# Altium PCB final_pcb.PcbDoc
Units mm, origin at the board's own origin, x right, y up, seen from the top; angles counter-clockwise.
Board outline 84.84 x 58.93 mm, 2 copper layers (Top Layer, Bottom Layer); 68 components, 48 nets, 240 pads, 41 vias.
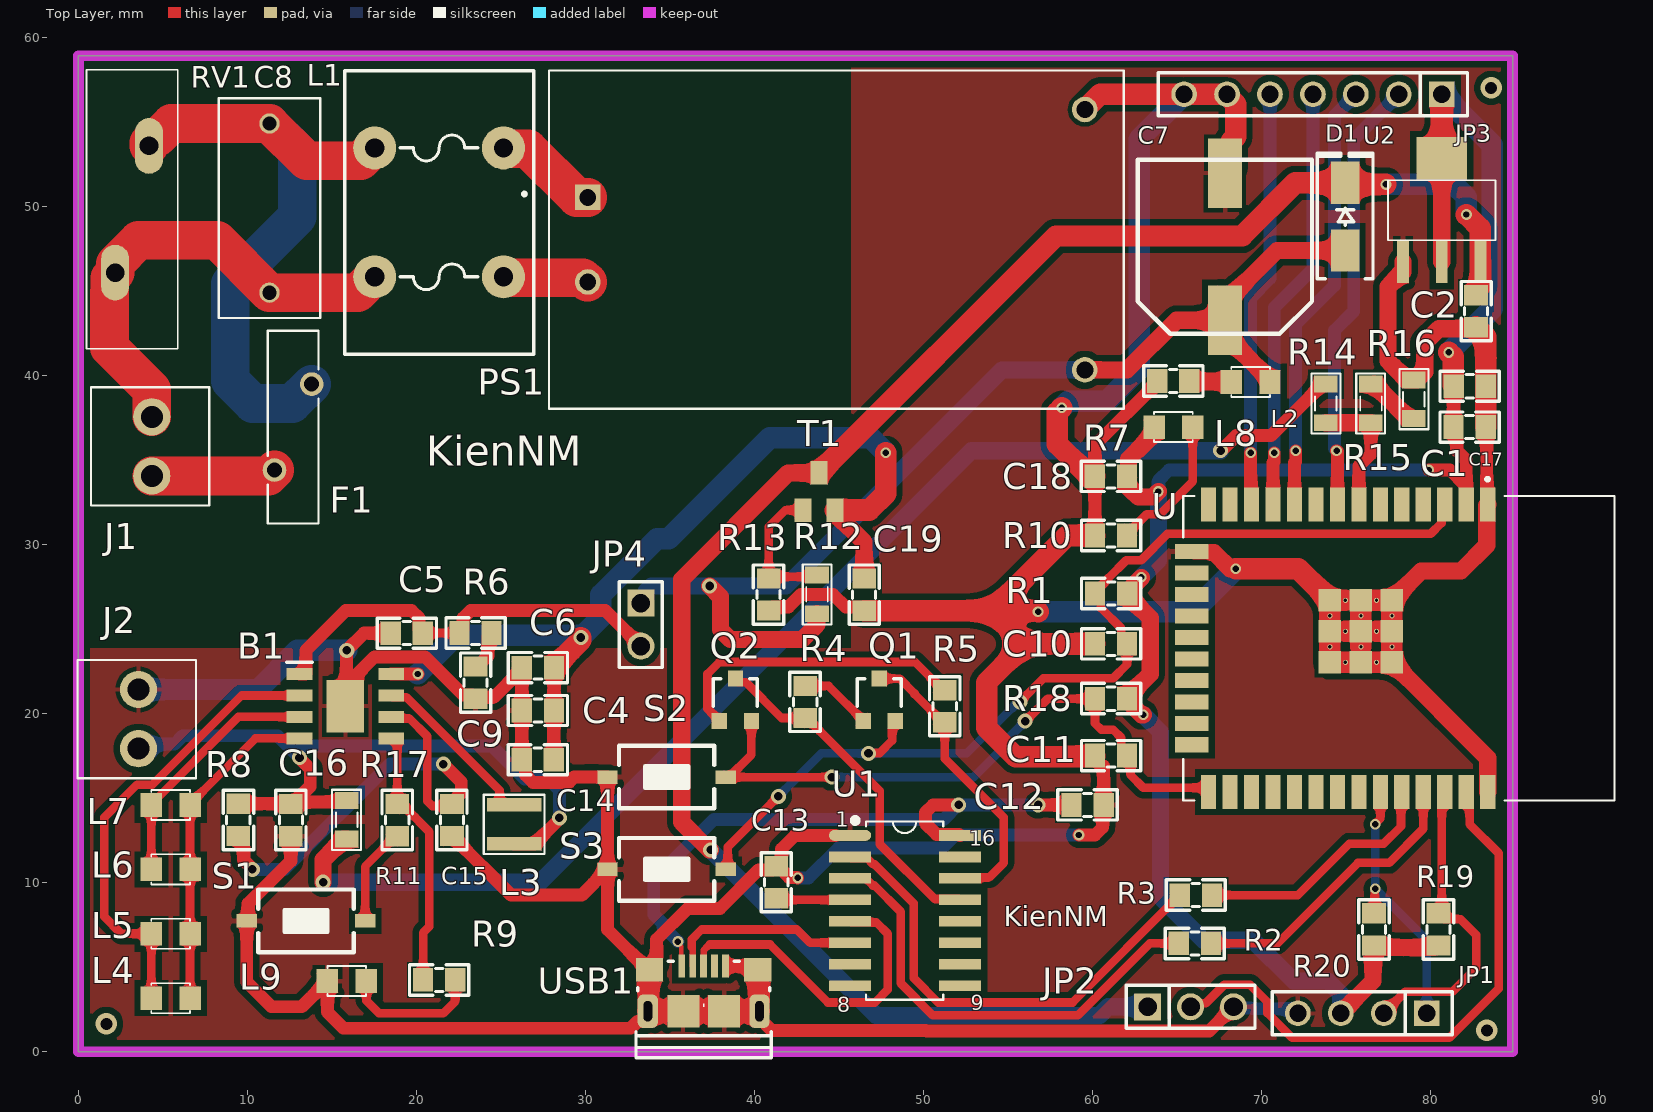
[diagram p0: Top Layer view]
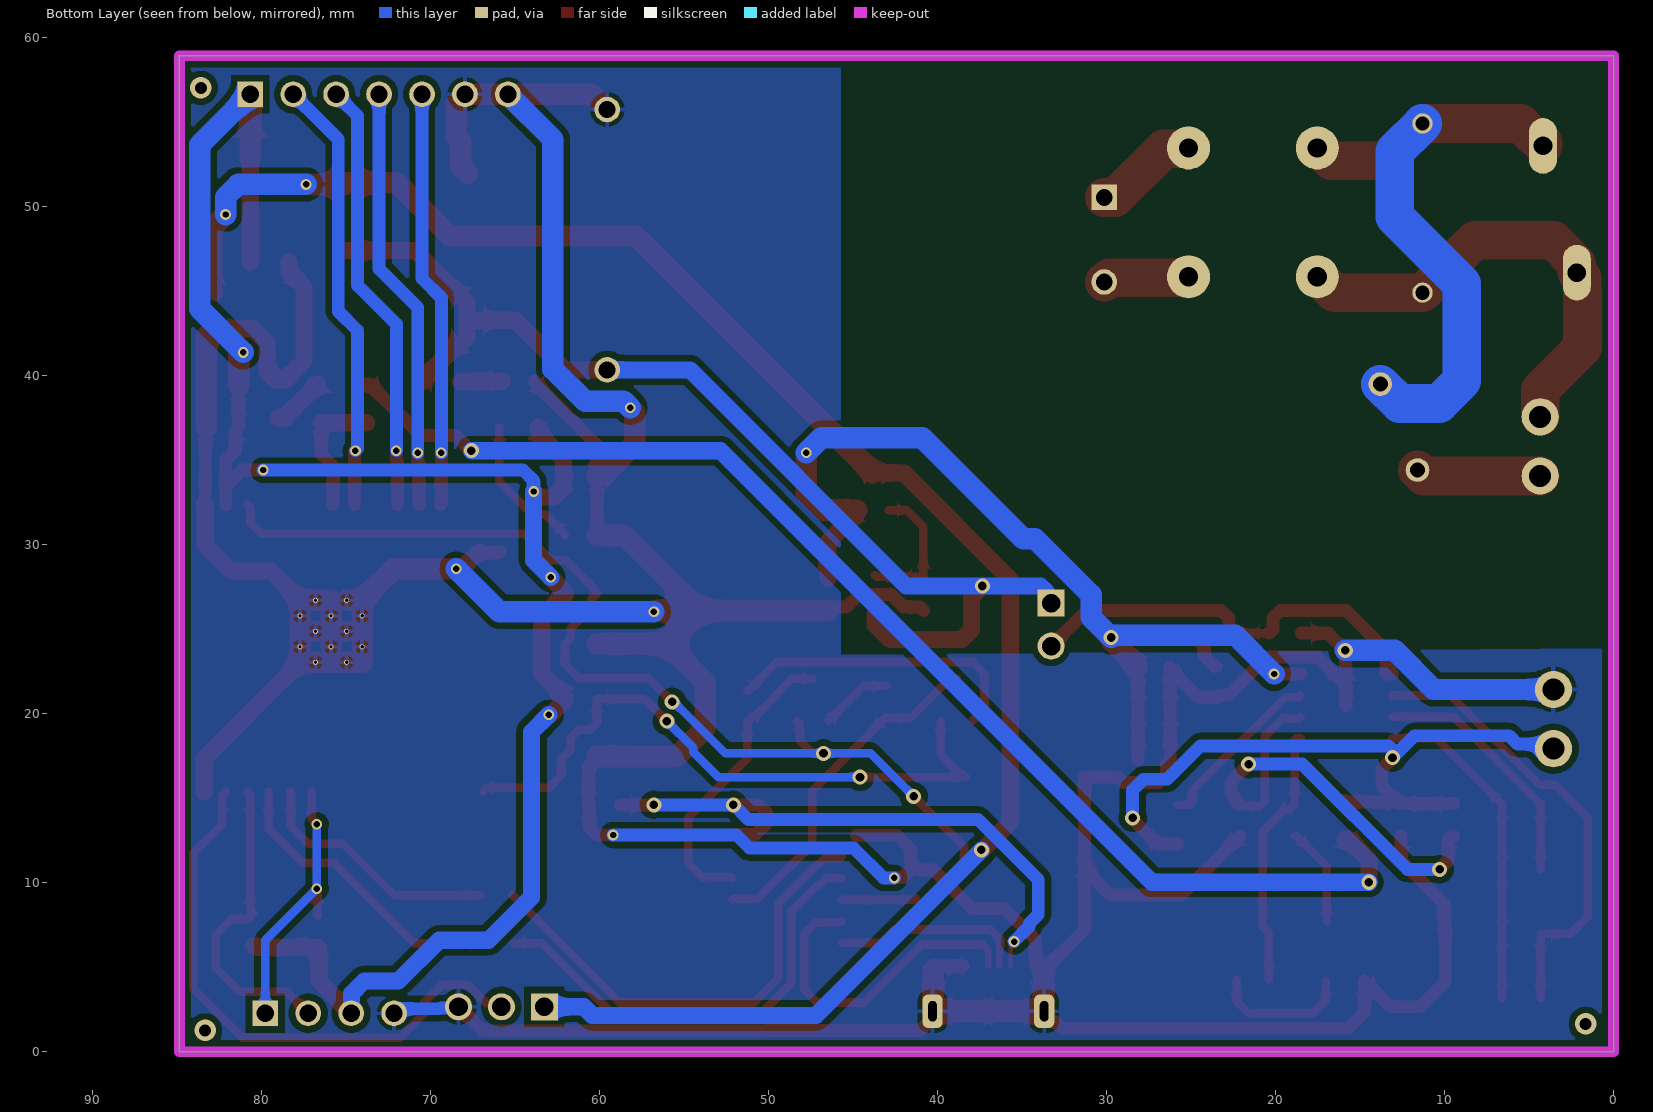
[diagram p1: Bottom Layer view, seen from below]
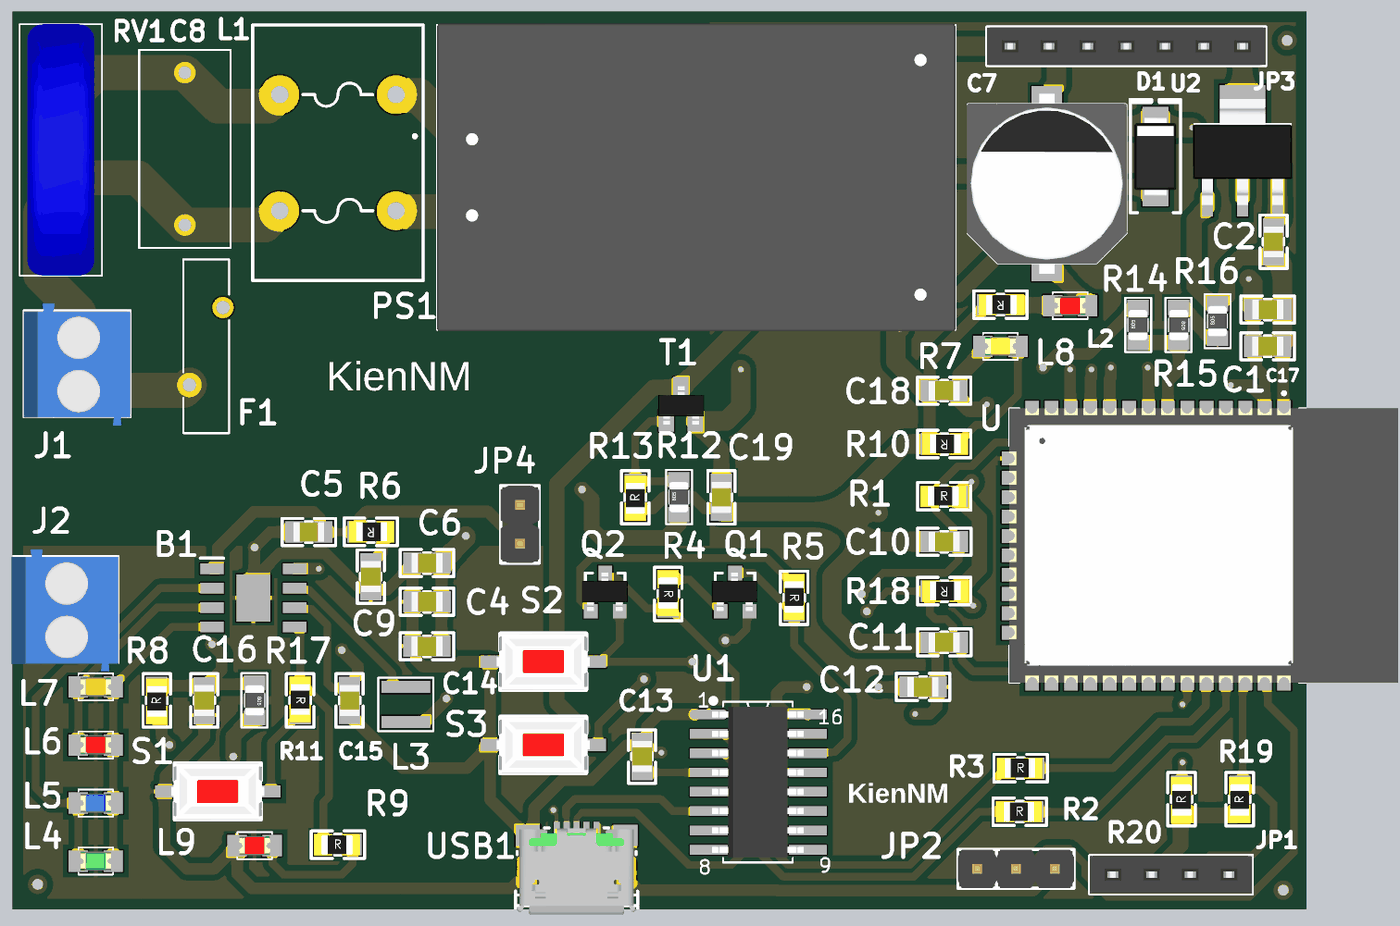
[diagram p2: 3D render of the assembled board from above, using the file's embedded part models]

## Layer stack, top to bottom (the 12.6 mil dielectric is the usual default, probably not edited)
Top Solder: solder mask 0.0102, Solder Resist, Dk 3.5
Top Layer: signal copper 0.0356
Dielectric 1: dielectric 0.32, FR-4, Dk 4.8
Bottom Layer: signal copper 0.0356
Bottom Solder: solder mask 0.0102, Solder Resist, Dk 3.5

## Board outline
0,0 84.836,0 84.836,58.928 0,58.928

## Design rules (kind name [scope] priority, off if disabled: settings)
Clearance [All] p1: gap=0.254 ignorepadtopadclearanceinfootprint=FALSE
PolygonConnect [All] p1: connectstyle=Relief reliefconductorwidth=0.254 reliefentries=4 polygonreliefangle="90 Angle" airgapwidth=0.254
RoutingVias [All] p1: holewidth=0.508 width=0.889 viastyle="Through Hole" minholewidth=0.381 minwidth=0.635 maxholewidth=0.711 maxwidth=1.27
SilkToSilkClearance [IsText] p1: silktosilkclearance=0.254
SolderMaskExpansion [All] p1: expansion=0.102 istentingtop=FALSE
Width [All] p1: maxlimit=1.27 minlimit=0.254 preferedwidth=0.762
29 further rules are at their usual default settings.

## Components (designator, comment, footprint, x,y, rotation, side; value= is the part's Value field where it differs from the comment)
B1 "IP5306" SOIC127P600X165-9N 15.793,20.447 r0 top
C1 "104" "tu 0805" 82.296,36.957 r180 top
C2 "224" "tu 0805" 82.296,39.37 r0 top
C4 "22uf" "tu 0805" 27.178,20.193 r0 top
C5 "106" "tu 0805" 19.431,24.765 r180 top
C6 "22uf" "tu 0805" 27.178,22.733 r0 top
C7 "220uF" "tu nhom 10 (g)" 67.818,47.625 r90 top
C8 "capacitor fillter" CAPRR1000W60L1300T600H1200 11.303,49.911 r90 top
C9 "106" "tu 0805" 23.495,21.844 r270 top
C10 "104" "tu 0805" 61.087,24.13 r180 top
C11 "104" "tu 0805" 61.087,17.526 r180 top
C12 "104" "tu 0805" 59.69,14.605 r0 top
C13 "104" "tu 0805" 41.275,10.033 r90 top
C14 "22uf" "tu 0805" 27.178,17.272 r180 top
C15 "22uf" "tu 0805" 22.098,13.713 r90 top
C16 "22uf" "tu 0805" 12.573,13.713 r270 top
C17 "106" "tu 0805" 82.677,43.815 r270 top
C18 "106" "tu 0805" 61.082,34.036 r180 top
C19 "22uf" "tu 0805" 46.482,27.048 r270 top
D1 "SS14" "DIODE SMA" 74.93,49.403 r90 top
F1 "fuse" F2-5.1-11.4X3.0X18.3MM 12.7,36.957 r90 top
J1 "KF2" KF2-3.5 4.342,35.814 r270 top
J2 "KF2" KF2-3.5 3.556,19.685 r270 top
JP1 "JP 1x4 2.54" "JP 1x4 CT" 79.756,2.286 r180 top
JP2 "JP 1x3 2.54" "JP 1x3 DT" 63.246,2.667 r0 top
JP3 "JP 1x7 2.54" "JP 1x7 CT" 80.645,56.642 r180 top
JP4 "JP 1x2 2.54" "JP 1x2 DT" 33.274,26.543 r270 top
L1 "L" L-DIP-220 20.066,48.387 r0 top value="Loc 220"
L2 "LED 0805" LED-0805-Red 70.485,39.624 r180 top
L3 "1 uH" IND_90.5_141.7_125X31_SMD 25.781,14.605 r0 top
L4 "" LED-0805-Green 4.318,3.175 r0 top
L5 "" LED-0805-Blue 6.604,6.985 r180 top
L6 "" LED-0805-Red 4.318,10.795 r0 top
L7 "" LED-0805-Orange 6.604,14.605 r180 top
L8 "LED 0805" LED-0805-Yellow 63.627,36.957 r0 top
L9 "LED 0805" LED-0805-Red 17.018,4.191 r180 top
PS1 "HLK-PM01" CONV_HLK-PM01 44.831,48.041 r0 top
Q1 "HF" SOT23 47.371,20.828 r0 top value=C9014
Q2 "HF" SOT23 38.862,20.828 r0 top value=C9014
R1 "10k" "tro smd 0805" 61.084,27.178 r0 top
R2 "0R" "tro smd 0805" 66.04,6.477 r0 top
R3 "0R" "tro smd 0805" 66.097,9.332 r0 top
R4 "10k" "tro smd 0805" 43.053,20.701 r270 top
R5 "10k" "tro smd 0805" 51.308,20.447 r270 top
R6 "2R" "tro smd 0805" 23.495,24.714 r180 top
R7 "1k" "tro smd 0805" 64.77,39.624 r180 top
R8 "0.5R" "tro smd 0805" 9.398,13.716 r90 top
R9 "22R" "tro smd 0805" 21.336,4.318 r0 top
R10 "1k" "tro smd 0805" 61.084,30.48 r180 top
R11 "10k" "tro smd 0805" 18.923,13.716 r270 top
R12 "1k" RES-SMD-0805 43.688,27.059 r90 top
R13 "10k" "tro smd 0805" 40.767,27.051 r90 top
R14 "10k" RES-SMD-0805 73.787,38.354 r90 top
R15 "1k" RES-SMD-0805 76.454,38.354 r270 top
R16 "0R" RES-SMD-0805 78.994,38.608 r90 top
R17 "0R" RES-SMD-0805 15.875,13.724 r270 top
R18 "10k" "tro smd 0805" 61.084,20.828 r180 top
R19 "10k" "tro smd 0805" 80.391,7.239 r90 top
R20 "10k" "tro smd 0805" 76.581,7.239 r90 top
RV1 "varistor" MOV14D471K 3.175,49.841 r270 top
S1 "SW-SMD" SW-SMD 13.462,7.747 r180 top
S2 "SW-SMD" SW-SMD 34.798,16.256 r0 top
S3 "SW-SMD" SW-SMD 34.798,10.795 r0 top
T1 "A03401" A3401 43.815,33.147 r0 top
U "ESP32-WROOM-32" MODULE_ESP32-WROOM-32 78.105,23.876 r270 top
U1 "CH340C" SOIC16_50_284_25X90_SMT 48.895,8.382 r0 top
U2 "LM1117-ADJ" LM1117-SOP 80.645,48.006 r0 top
USB1 "USB Micro 5p DIP" "USB Micro 5p DIP" 36.984,2.405 r0 top

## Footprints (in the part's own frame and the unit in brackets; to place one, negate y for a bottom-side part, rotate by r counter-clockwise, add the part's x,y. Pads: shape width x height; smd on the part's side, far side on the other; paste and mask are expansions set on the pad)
A3401 [mm] "P-Channel 30V 4A _Ta_ 1.4W _Ta_ Surface Mount SOT-23-3"
  rect 1x1.4 smd: 1(-0.95,-1.1) 2(0.95,-1.1) 3(0,1.1)
  body extent -1.47,-1.33 1.53,1.17, height 1.06
CAPRR1000W60L1300T600H1200 [mm]
  round 1.2 hole 0.85: 1(-5,0) 2(5,0)
  silkscreen extent -6.5,-3 6.5,3
CONV_HLK-PM01 [mm]
  rect 1.508x1.508 / inner round 1.508 / far side rect 1.508x1.508 hole 1: 1(-14.7,2.5)
  round 1.508 hole 1: 2(-14.7,-2.5) 3(14.7,7.7) 4(14.7,-7.7)
  silkscreen extent -18.55,-10 17,10, body extent -17,-10.1 17,10.1, height 15
"DIODE SMA" [mm] "SMA"
  rect 2.5x1.7 smd: 1(-2,0) 2(2,0)
  silkscreen extent -3.68,-1.65 3.75,1.65, body extent -2.6,-1.37 2.6,1.37, height 2.4
F2-5.1-11.4X3.0X18.3MM [mil]
  round 55 hole 35: 1(-100,43.31) 2(100,-43.31)
  silkscreen extent -224,-59 224,59
IND_90.5_141.7_125X31_SMD [mm] "Inductor"
  rect 3.2x0.8 smd: 1(0,0) 2(0,-2.3)
  silkscreen extent -1.8,-2.9 1.8,0.6
"JP 1x2 DT" [mm] "2 pins, 1 row, straight, gold plating"
  rect 1.6x1.6 hole 1.1: 1(0,0)
  round 1.6 hole 1.1: 2(2.54,0)
  silkscreen extent -1.27,-1.27 3.81,1.27, body extent -1.27,-1.27 3.81,1.27, height 8.54
"JP 1x3 DT" [mm]
  rect 1.6x1.6 hole 1.1: 1(0,0)
  round 1.6 hole 1.1: 2(2.54,0) 3(5.08,0)
  silkscreen extent -1.27,-1.27 6.35,1.27, body extent -1.27,-1.27 6.35,1.27, height 8.54
"JP 1x4 CT" [mm]
  rect 1.52x1.52 hole 1.02: 1(0,0)
  round 1.52 hole 1.02: 2(2.54,0) 3(5.08,0) 4(7.62,0)
  silkscreen extent -1.52,-1.27 9.14,1.27, body extent -1.52,-1.25 9.14,1.25, height 8.51
"JP 1x7 CT" [mm] "7 row, straight, gold plating"
  rect 1.52x1.52 hole 1.02: 1(0,0)
  round 1.52 hole 1.02: 2(2.54,0) 3(5.08,0) 4(7.62,0) 5(10.16,0) 6(12.7,0) 7(15.24,0)
  silkscreen extent -1.52,-1.27 16.76,1.27, body extent -1.52,-1.25 16.76,1.25, height 8.51
KF2-3.5 [mm] "3,50mm - modular - blue - Horizontal wire entry - Pressure clamp - 8,4mm height - 02p"
  round 2.2 hole 1.3: 1(-1.75,0) 2(1.75,0)
  silkscreen extent -3.5,-3.6 3.5,3.4, body extent -3.95,-3.6 4.05,3.4, height 8.41
L-DIP-220 [mil] "Loc 220"
  round 100 hole 45: 1(-100,-100) 2(200,-100) 3(200,200) 4(-100,200)
  silkscreen extent -170,-280 270,380
LED-0805-Blue [mil]
  rect 50x55 smd: 1(0,0) 2(90,0)
  silkscreen extent 0,-35 90,35, body extent 5,-25 85,25, height 43
LED-0805-Green [mil]
  rect 50x55 smd: 1(0,0) 2(90,0)
  silkscreen extent 0,-35 90,35, body extent 5,-25 85,25, height 43
LED-0805-Orange [mil]
  rect 50x55 smd: 1(0,0) 2(90,0)
  silkscreen extent 0,-35 90,35, body extent 5,-25 85,25, height 43
LED-0805-Red [mil]
  rect 50x55 smd: 1(0,0) 2(90,0)
  silkscreen extent 0,-35 90,35, body extent 5,-25 85,25, height 43
LED-0805-Yellow [mil]
  rect 50x55 smd: 1(0,0) 2(90,0)
  silkscreen extent 0,-35 90,35, body extent 5,-25 85,25, height 43
LM1117-SOP [mm]
  rect 0.7x2.54 smd: 1(-2.3,-1.27) 2(0,-1.27) 3(2.3,-1.27)
  rect 3x2.54 smd: 2(0,4.826)
  silkscreen extent -3.17,0 3.17,3.56, body extent -3.25,-1.78 3.25,5.18, height 1.68
MODULE_ESP32-WROOM-32 [mm]
  rect 2x0.9 smd: 1(-8.5,5.26) 2(-8.5,3.99) 3(-8.5,2.72) 4(-8.5,1.45) 5(-8.5,0.18) 6(-8.5,-1.09) 7(-8.5,-2.36) 8(-8.5,-3.63) 9(-8.5,-4.9) 10(-8.5,-6.17) 11(-8.5,-7.44) 12(-8.5,-8.71) 13(-8.5,-9.98) 14(-8.5,-11.25) 25(8.5,-11.25) 26(8.5,-9.98) 27(8.5,-8.71) 28(8.5,-7.44) 29(8.5,-6.17) 30(8.5,-4.9) 31(8.5,-3.63) 32(8.5,-2.36) 33(8.5,-1.09) 34(8.5,0.18) 35(8.5,1.45) 36(8.5,2.72) 37(8.5,3.99) 38(8.5,5.26)
  rect 0.9x2 smd: 16(-4.445,-12.25) 17(-3.175,-12.25) 18(-1.905,-12.25) 19(-0.635,-12.25) 20(0.635,-12.25) 21(1.905,-12.25) 22(3.175,-12.25) 23(4.445,-12.25) 24(5.715,-12.25) C(-5.715,-12.25)
  rect 1.33x1.33 smd: 39_1(-2.835,-0.405) 39_2(-1,-0.405) 39_3(0.835,-0.405) 39_4(-2.835,-2.24) 39_5(-1,-2.24) 39_6(0.835,-2.24) 39_7(-2.835,-4.075) 39_8(-1,-4.075) 39_9(0.835,-4.075)
  round 0.3 hole 0.2: 39_10(-1.917,-0.405) 39_11(-0.082,-0.405) 39_12(-2.835,-1.322) 39_13(-1,-1.322) 39_14(0.835,-1.322) 39_15(-1.917,-2.24) 39_16(-0.082,-2.24) 39_17(-2.835,-3.157) 39_18(-1,-3.157) 39_19(0.835,-3.157) 39_20(-1.917,-4.075) 39_21(-0.082,-4.075)
  silkscreen extent -10.1,-12.75 9,12.75, body extent -9.02,-12.75 8.98,12.75, height 3.2
MOV14D471K [mm]
  oval 3.3x1.65 hole 1.1: 1(-3.75,1) 2(3.75,-1)
  silkscreen extent -8.25,-2.7 8.25,2.7, body extent -8.25,-2.2 8.25,2.2, height 20
RES-SMD-0805 [mil]
  rect 39.37x55 smd: 1(-45,0) 2(45,0)
  silkscreen extent -70,-34 70,33, body extent -39,-25 39,25, height 31
SOIC16_50_284_25X90_SMT [mm]
  oval 2.5x0.635 smd mask+0.076: 1(-3.25,4.42)
  rect 2.5x0.635 smd mask+0.076: 2(-3.25,3.15) 3(-3.25,1.88) 4(-3.25,0.61) 5(-3.25,-0.66) 6(-3.25,-1.93) 7(-3.25,-3.2) 8(-3.25,-4.47) 9(3.25,-4.47) 10(3.25,-3.2) 11(3.25,-1.93) 12(3.25,-0.66) 13(3.25,0.61) 14(3.25,1.88) 15(3.25,3.15) 16(3.25,4.42)
  silkscreen extent -3.07,-5.3 2.26,5.44, body extent -3.02,-4.97 2.98,4.93, height 1.4
SOIC127P600X165-9N [mm]
  rect 1.525x0.7 smd: 1(-2.712,1.905) 2(-2.712,0.635) 3(-2.712,-0.635) 4(-2.712,-1.905) 5(2.712,-1.905) 6(2.712,-0.635) 7(2.712,0.635) 8(2.712,1.905)
  rect 2.21x3.1 smd: 9(0,0)
  silkscreen extent -3.47,2.61 -1.95,2.61
SOT23 [mm] "SOT23"
  rect 0.9x0.95 smd: 1(-0.95,-1.25) 2(0,1.25)
  rect 0.9x0.95 smd mask+0: 3(0.95,-1.25)
  silkscreen extent -1.3,-0.38 1.3,1.25, body extent -1.52,-1.23 1.48,1.27, height 1.06
SW-SMD [mm] "Switch SMD type"
  rect 1.2x0.8 smd: 1(-3.5,0) 2(3.5,0)
  silkscreen extent -2.82,-1.85 2.82,1.85, body extent -3.05,-1.85 3.05,1.85, height 2.5
"tro smd 0805" [mm]
  rect 1.2x1.4 smd: 1(-0.946,-0.061) 2(0.954,-0.061)
  silkscreen extent -1.75,-0.97 1.75,0.84, body extent -1.56,-0.76 1.44,0.64, height 0.53
"tu 0805" [mm] "Compoment SMD 80x50mil"
  rect 1.2x1.4 smd: 1(-0.946,-0.003) 2(0.954,-0.003)
  silkscreen extent -1.75,-0.89 1.75,0.89, body extent -1.01,-0.64 1.01,0.63, height 0.61
"tu nhom 10 (g)" [mm]
  rect 4.1x2 smd: 1(-4.35,0) 2(4.35,0)
  silkscreen extent -5.15,-5.15 5.15,5.15, body extent -5.9,-5.25 5.9,5.25, height 10.5
"USB Micro 5p DIP" [mm]
  rect 0.4x1.35 smd mask+0.05: 1(-1.3,2.675) 2(-0.65,2.675) 3(0,2.675) 4(0.65,2.675) 5(1.3,2.675)
  rrect60% 1.2x2 hole 0.5 slot 1.2 at 90 deg: 5(-3.3,0) 5(3.3,0)
  rect 1.6x1.4 smd: 5(-3.2,2.45) 5(3.2,2.45)
  rect 1.9x1.9 smd paste-10: 5(-1.2,0) 5(1.2,0)
  silkscreen extent -4,-2.75 4,2.95, body extent -3.93,-2.76 3.93,2.9, height 2.85

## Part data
B1: "Fully-Integrated Power-Bank System-On-Chip", Manufacturer_Name=INJOINIC
C1 C10 C11 C12 C13: library part "Tu 0805 104 50V 10%", "Dán"
C2: library part "Tu 0805 224 50V 10%", "Dán"
C4 C6 C14 C15 C16 C19: library part "Tu 0805 225 25V 10%", "Dán"
C5 C9 C17 C18: library part "Tu 0805 106 16V 10%", "Dán"
C7: library part "Tu Nhom 220uF 50V", "Dán"
C8: library part B32921C3104M003, "Safety Capacitors FILM CAP MKP X2 0.10uF 20% 305Vac LS 10mm - short leads", Package=None
D1: library part "Diode SS14 ( 1N5819)", "Dán"
F1: library part DIP-PPTC-2.5A-30V(D11.4MM), "Polymeric PTC Resettable Fuse 30V 2.5A Ih Through Hole Radial, Disc", Package="Radial Littelfuse"
J1 J2: Manufacturer="Würth Elektronik eiSos GmbH", partNo=691103110002
JP1: library part "JP 1x4 2.54 Cai Thang", "Cắm"
JP2: library part "JP 1x3 2.54 Duc Thang", "Cắm"
JP3: library part "JP 1x7 2.54 Cai Thang", "Cắm"
JP4: library part "JP 1x2 2.54 Duc Thang", "Cắm"
L1: library part L-DIP-220, "Inductor"
L2 L6 L9: library part "LED 0805 Do", "Dán"
L3: library part IND_1uH-4.2A-20%-SMD, "Fixed Inductors WPN3012H1R0MT 100kHz", Alternate Part Number-1=NA, Case/Package=SMD, Manufacturer=Sunlord, Manufacturer Part Number=WPN3012H1R0MT
L4: library part "LED 0805 Xanh La", "Dán"
L5: library part "LED 0805 Xanh Duong", "Dán"
L7: library part "LED 0805 Cam", "Dán"
L8: library part "LED 0805 Trang", "Dán"
PS1: "The HLK-PM01 is a small size low cost AC to DC converter which can take in 110V/220V AC at 50/60 Hz and give 5V 3W output. The module is can be used in designs which run on 5V and needs to be powered form the AC mains.", Package=None
Q1 Q2: library part "C1815 HF SMD", "NPN transistor"
R1 R4 R5 R18: library part "Tro 0805 5% 10k", "Dán"
R2 R3: library part "Tro 0805 5% 0R", "Dán"
R6: library part "Tro 0805 5% 1R", "Dán"
R7 R10: library part "Tro 0805 1% 1k", "Dán"
R8: library part "Tro 0805 1% 0.5R", "Dán"
R9: library part "Tro 0805 5% 22R", "Dán"
R11 R13 R19 R20: library part "Tro 0805 1% 10k", "Dán"
R12 R14 R15 R16 R17: library part "Resistor - SMD", "Resistor", Manufacturer="Generic Components"
RV1: library part MOV-14D471K, "470 V 4.5 kA Varistor 1 Circuit Through Hole Disc 14mm", Package="Disc-14 Bourns"
S1 S2 S3: "Switch"
T1: "P-Channel 30V 4A _Ta_ 1.4W _Ta_ Surface Mount SOT-23-3"
U: "Bluetooth, WiFi Transceiver Module 2.4GHz ~ 2.5GHz Surface Mount", Package="Module Espressif Systems"
U1: "USB Bridge, USB to UART USB 2.0 UART Interface", Alternate Part Number-1=NA, Case/Package=SOIC16, Manufacturer=Olimex, Supplier Part Number-1=C84681
U2: "800mA Low-Dropout Linear Regulator"
USB1: "USB Type B"

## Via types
v1: diameter 0.635, hole 0.381, Top Layer to Bottom Layer, tented both sides, 21 vias
v2: diameter 0.889, hole 0.508, Top Layer to Bottom Layer, tented both sides, 17 vias
v3: diameter 1.27, hole 0.711, Top Layer to Bottom Layer, tented both sides, 3 vias

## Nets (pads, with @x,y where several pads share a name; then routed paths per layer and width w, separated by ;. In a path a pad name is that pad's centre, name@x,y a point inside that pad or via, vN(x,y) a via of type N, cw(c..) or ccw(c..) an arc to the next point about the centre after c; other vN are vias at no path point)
3V3: C1.2 C2.1 C18.1 JP1.3 JP3.1 L8.1 R1.2 R18.1 R19.1 R20.1 U2.2 U.2 | length 112.1
  Top Layer w0.762: v1(79.883,34.417) 81.132,34.417 82.026,33.523 ; C2.1@81.346,39.337 81.346,36.965 C1.2 81.529,36.773 81.529,35.565 82.095,34.999 U.2 ; C2.1@81.346,39.362 C2.1
  Top Layer w1.016: v1(62.865,28.067) 62.865,28.043 62.039,27.217 R1.2 62.039,27.017 63.398,25.658 63.398,22.357 62.03,20.989 R18.1 62.03,20.789 62.88,19.939 v1(62.992,19.939) ; L8.1 63.5,36.83 63.5,36.449 62.119,35.068 62.119,34.131 C18.1 62.119,33.947 62.119,33.417 62.715,32.822 63.556,32.822 v1(63.881,33.147) ; JP1.3 76.581,4.191 76.581,6.106 76.642,6.166 80.225,6.166 80.352,6.293 R19.1 ; U2.2@80.645,46.736 U2.2@80.645,52.832
  Top Layer w1.27: U2.2@80.645,52.832 JP3.1 ; v1(81.055,41.372) 81.315,41.111 C2.1@81.315,39.432
  Bottom Layer w0.762: v1(63.881,33.147) 63.881,33.782 64.516,34.417 v1(79.883,34.417)
  Bottom Layer w1.016: v1(62.865,28.067) 63.881,29.083 v1(63.881,33.147) ; v1(62.992,19.939) 64.008,18.923 64.008,9.144 66.548,6.604 69.469,6.604 71.882,4.191 73.914,4.191 74.648,3.457 74.648,2.314 JP1.3
  Bottom Layer w1.27: JP3.1 83.629,53.657 83.629,43.947 v1(81.055,41.372)
5V_REG: C7.1 D1.1 JP4.1 L2.1 PS1.4 R12.1 | length 65.8
  Top Layer w1.016: v2(37.338,27.559) 37.973,26.924 37.973,24.979 38.568,24.384 42.799,24.384 43.688,25.273 R12.1 ; PS1.4 62.028,40.341 64.962,43.275 C7.1 ; L2.1 70.358,39.751 70.358,39.876 68.501,41.733 68.31,41.733 67.818,42.225 C7.1 ; D1.1 70.896,47.403 67.818,44.325 C7.1
  Bottom Layer w1.016: JP4.1 33.566,26.835 33.566,27.228 33.897,27.559 v2(37.338,27.559) 41.854,27.559 54.635,40.341 PS1.4
AC_IN1: F1.1 J1.2 | length 7.4
  Top Layer w2.286: J1.2 11.247,34.064 F1.1
AC_IN2: C8.1 J1.1 L1.1 RV1.2 | length 27.8
  Top Layer w2.286: J1.1 4.342,39.162 1.841,41.663 1.841,44.932 1.857,44.948 1.857,45.773 RV1.2 2.175,46.625 3.556,48.006 8.208,48.006 C8.1 16.521,44.911 17.457,45.847 L1.1
D+: U1.5 USB1.3 | length 19.5
  Top Layer w0.381: USB1.3 36.987,5.083 36.987,5.999 37.338,6.35
  Top Layer w0.508: 37.338,6.35 40.907,6.35 44.336,2.921 47.117,2.921 47.879,3.683 47.879,6.985 47.205,7.659 45.708,7.659 U1.5
D-: U1.6 USB1.2 | length 11.5
  Top Layer w0.381: 36.291,6.177 36.334,6.134 USB1.2
  Top Layer w0.508: 36.291,6.177 36.291,6.666 36.864,7.239 42.495,7.239 43.282,6.452 U1.6
DTR: Q2.2 R4.2 U1.13 | length 20.5
  Top Layer w0.508: Q2.2 38.862,22.053 39.058,21.857 39.484,21.857 41.594,19.747 R4.2 ; R4.2@43.042,19.797 47.403,15.436 47.403,12.287 50.634,9.056 52.082,9.056 U1.13
EN: C10.1 Q1.3 R1.1 S3.2 U.3 | length 60.9
  Top Layer w0.508: S3.2 38.298,10.826 38.413,10.941 38.413,12.124 v2(41.402,15.113) ; v2(46.736,17.653) 46.764,17.681 47.399,17.681 48.133,18.415 48.133,19.39 Q1.3 ; v2(55.689,20.701) 57.085,22.097 61.213,22.097 62.033,22.917 C10.1 61.687,24.479 61.687,25.054 60.485,26.256 60.485,26.771 R1.1 60.139,27.217 60.931,28.009 60.931,28.028 61.986,29.083 62.865,29.083 64.423,30.641 79.988,30.641 80.629,31.282 80.629,32.18 U.3
  Bottom Layer w0.508: v2(41.402,15.113) 43.942,17.653 v2(46.736,17.653) 52.538,17.653 55.586,20.701 v2(55.689,20.701)
GND: B1.9 C1.1 C2.2 C4.1 C5.2 C6.1 C7.2 C9.2 C10.2 C11.2 C12.2 C13.2 C14.2 C15.1 C16.2 C17.2 C18.2 C19.2 J2.1 JP1.4 JP2.3 JP3.6 JP3.7 L9.2 PS1.3 R7.2 R10.2 R13.1 R16.2 S1.2 S2.1 S3.1 U1.1 U2.1 U.1 U.38 U.39_1 U.39_2 U.39_3 U.39_4 U.39_5 U.39_6 U.39_7 U.39_8 U.39_9 U.39_10 U.39_11 U.39_12 U.39_13 U.39_14 U.39_15 U.39_16 U.39_17 U.39_18 U.39_19 U.39_20 U.39_21 U.C USB1.5 | length 375.6
  Top Layer w0.254: USB1.5@39.774,4.445 USB1.5@40.184,4.855
  Top Layer w0.762: C16.2 12.57,11.3 10.036,8.766 10.036,7.766 10.017,7.747 S1.2 9.962,4.135 11.43,2.667 13.208,2.667 14.414,3.873 14.478,3.873 L9.2@14.732,4.127 ; L9.2 L9.2@14.732,4.127 ; B1.9 15.851,20.505 15.851,20.95 15.851,21.651 15.851,23.725 v2(15.875,23.749) 16.894,24.768 C5.2 ; B1.9@15.793,20.95 15.793,21.651 17.056,22.913 17.51,23.368 20.505,23.368 22.765,21.109 23.273,21.109 C9.2 23.584,20.982 24.584,20.982 C6.1@26.232,22.63 ; C15.1 25.598,9.271 29.774,9.271 S3.1 ; C6.1 C6.1@26.232,22.63 ; USB1.5@33.684,2.405 33.684,2.005 33.465,1.786 33.065,1.786 32.676,1.397 15.684,1.397 14.732,2.349 14.732,3.873 L9.2@14.732,4.127 ; USB1.5@38.469,5.08 39.959,5.08 USB1.5@40.184,4.855 ; USB1.5@40.284,2.405 40.284,2.005 41.019,1.27 50.121,1.27 50.159,1.232 66.891,1.232 JP2.3 ; R13.1 41.047,26.324 41.999,26.324 42.734,27.059 44.642,27.059 45.388,26.313 46.26,26.313 C19.2 ; v1(42.545,10.287) 42.51,10.322 42.043,10.322 C13.2@41.378,10.987 ; U1.1@44.776,12.791 42.382,12.791 41.597,12.006 41.597,11.206 C13.2@41.378,10.987 ; v1(59.182,12.827) 60.134,12.827 60.58,13.273 60.58,14.537 C12.2 ; C18.2 60.129,34.038 R10.2 R10.2 ; C18.2@60.127,34.069 60.127,35.897 63.816,39.585 R7.2 ; C12.2@60.644,14.502 C12.2 ; C11.2@60.644,16.918 C12.2 ; U.C 65.913,29.533 66.987,29.533 ; C1.1 83.303,36.899 U.1@83.303,32.438 ; C6.1@26.232,22.63 C4.1 26.228,20.185 26.228,17.28 C14.2 26.443,17.056 26.443,16.387 26.889,15.94 29.012,15.94 29.328,16.256 S2.1 S3.1 ; S3.1 31.298,7.241 33.684,4.855 33.784,4.855 33.884,4.855 34.203,5.174 34.203,6.644 36.043,8.484 37.948,8.484 40.232,10.768 41.059,10.768 C13.2 C13.2@41.378,10.987
  Top Layer w1.016: 66.987,29.533 67.171,29.533 68.129,28.575 v1(68.453,28.575) ; U.39_3 83.365,17.376 U.38 ; U.39_1 79.437,28.448 81.788,28.448 83.307,29.967 83.307,32.318 U.1 ; U2.1 78.345,46.132 77.47,45.257 77.47,40.867 78.578,39.759 78.986,39.759 R16.2 79.177,39.751 79.658,40.232 79.658,41.95 80.476,42.769 82.582,42.769 C17.2
  Top Layer w1.27: USB1.5@33.784,4.855 33.719,4.79 33.719,2.44 33.684,2.405 35.784,2.405 38.184,2.405 40.284,2.405 40.249,2.44 40.249,4.79 USB1.5@40.184,4.855 ; C19.2 54.043,26.094 ; v1(56.769,26.035) 56.71,26.094 54.043,26.094 ; v1(58.166,38.1) 57.912,37.846 57.912,35.941 59.749,34.104 60.092,34.104 60.127,34.069 C18.2 ; PS1.3 60.432,56.642 JP3.7@65.337,56.642 ; R10.2 58.49,30.541 54.043,26.094 ; C11.2 60.133,17.499 60.098,17.464 59.567,17.464 59.565,17.462 55.435,17.462 53.721,19.177 53.721,21.844 56.007,24.13 ; C10.2 60.129,24.13 56.007,24.13 ; JP3.7 JP3.6 67.945,56.574 68.453,56.066 68.453,54.134 68.183,53.864 68.183,52.34 C7.2 ; v1(68.453,28.575) 72.166,28.575 U.39_7 ; U.39_18 U.39_5 ; U.39_17 U.39_7 ; U.39_16 U.39_5 ; U.39_13 U.39_2 ; C17.2@82.669,42.896 83.25,42.314 C2.2 83.246,39.362 83.246,36.965 C1.1 ; 54.043,26.094 56.007,24.13 ; U.39_7 U.39_20 U.39_8 U.39_21 U.39_9 U.39_19 U.39_6 U.39_14 U.39_3 U.39_11 U.39_2 ; U.39_5 U.39_15 U.39_4 U.39_12 U.39_1 U.39_10 U.39_2
  Bottom Layer w0.762: v1(42.545,10.287) 43.18,10.287 44.958,12.065 51.117,12.065 51.879,12.827 v1(59.182,12.827) ; JP2.3 69.452,2.566 71.681,2.536 71.904,2.313 71.931,2.286 JP1.4
  Bottom Layer w1.27: J2.1 10.64,21.435 12.954,23.749 v2(15.875,23.749) ; v1(56.769,26.035) 65.913,26.035 v1(68.453,28.575) ; v1(58.166,38.1) 58.547,38.481 60.833,38.481 62.738,40.386 62.738,53.975 JP3.7
GND_ADC: R15.1 R16.1 | length 3.2
  Top Layer w1.016: R15.1@76.644,39.489 78.661,37.473 78.986,37.473 R16.1
IO0: C11.1 Q2.3 R18.2 S2.2 U.25 | length 38.6
  Top Layer w0.508: S2.2 S2.2@38.498,16.256 ; Q2.3 39.812,17.57 S2.2@38.498,16.256 ; v2(44.577,16.256) S2.2@38.498,16.256 ; v2(56.007,19.558) 57.338,20.889 R18.2 60.133,20.886 60.133,19.427 60.5,19.06 61.204,19.06 61.681,18.583 61.681,18.273 61.687,18.268 61.687,17.875 62.239,17.323 62.239,16.374 62.992,15.621 66.659,15.621 66.855,15.425 U.25
  Bottom Layer w0.508: v2(44.577,16.256) 52.959,16.256 54.447,17.744 54.447,17.998 v2(56.007,19.558)
IO25: JP3.3 U.10 | length 25.8
  Top Layer w0.762: U.10 71.935,34.851 72.009,34.925 v1(72.009,35.56)
  Bottom Layer w0.762: v1(72.009,35.56) 72.004,35.565 72.004,43.048 74.295,45.339 74.295,55.372 JP3.3
IO26: JP3.4 U.11 | length 25.2
  Top Layer w0.762: U.11 70.665,34.851 70.739,34.925 v1(70.739,35.433)
  Bottom Layer w0.762: v1(70.739,35.433) 70.739,44.03 73.025,46.316 JP3.4
IO27: JP3.5 U.12 | length 24.8
  Top Layer w0.762: v1(69.342,35.433) 69.342,32.429 U.12
  Bottom Layer w0.762: v1(69.342,35.433) 69.342,44.601 70.485,45.744 JP3.5
IO28: JP3.2 U.8 | length 25.9
  Top Layer w0.762: v1(74.422,35.56) 74.475,35.507 U.8
  Bottom Layer w0.762: v1(74.422,35.56) 74.295,35.687 74.295,42.672 75.438,43.815 75.438,53.975 JP3.2
NetB1_1: B1.1 C5.1 JP4.2 R6.2 | length 25.3
  Top Layer w0.508: C5.1 20.38,24.772 R6.2@22.537,24.772
  Top Layer w0.762: B1.1 13.432,22.352 13.463,22.383 13.463,23.75 15.816,26.103 19.711,26.103 20.158,25.657 20.158,24.987 C5.1 ; R6.2 22.76,24.994 22.76,25.664 23.206,26.11 31.167,26.11 JP4.2
NetB1_2: B1.2 L4.1 L5.2 | length 27.4
  Top Layer w0.508: L4.1 L5.2 2.54,6.985 1.524,8.001 1.524,13.863 3.473,15.811 4.381,15.811 9.652,21.082 B1.2
NetB1_3: B1.3 L6.1 L7.2 | length 14.8
  Top Layer w0.508: L6.1 L7.2 4.318,14.668 9.461,19.812 B1.3
NetB1_4: B1.4 L4.2 L5.1 L6.2 L7.1 | length 19.6
  Top Layer w0.508: L4.2 L5.1 L6.2 L7.1 6.604,14.668 10.477,18.542 B1.4
NetB1_5: B1.5 R9.1 R11.1 | length 15.7
  Top Layer w0.508: B1.5 18.766,18.542 18.862,18.446 R11.1 19.208,14.316 19.466,14.316 20.758,13.024 20.758,7.414 20.39,7.047 R9.1
NetB1_6: B1.6 C15.2 R8.1 | length 27.4
  Top Layer w0.508: B1.6 18.601,19.716 19.592,19.716 20.639,18.669 20.639,14.841 20.937,14.543 C15.2@22.101,14.543
  Top Layer w0.762: R8.1 9.559,12.77 9.778,12.551 9.778,11.339 10.287,10.829 v2(10.287,10.795) ; v2(21.59,17.018) 21.592,17.018 22.645,15.964 22.645,15.333 22.42,15.108 22.42,14.887 22.201,14.668 C15.2
  Bottom Layer w0.762: v2(10.287,10.795) 12.192,10.795 18.415,17.018 v2(21.59,17.018)
NetB1_7: B1.7 L3.1 | length 10.4
  Top Layer w0.508: B1.7 18.601,20.986 19.4,20.986 24.917,15.469 24.917,14.751 25.063,14.605 L3.1
NetC8_2: C8.2 F1.2 L1.4 RV1.1 | length 38.6
  Top Layer w2.286: RV1.1 4.175,53.78 4.493,54.098 4.682,54.098 5.495,54.911 C8.2 13.509,52.705 16.695,52.705 17.457,53.467 L1.4
  Bottom Layer w2.286: C8.2 12.954,53.26 12.954,49.403 8.982,45.431 8.982,39.693 10.322,38.354 12.657,38.354 F1.2
NetC9_1: C9.1 R6.1 | length 2.4
  Top Layer w0.762: C9.1 23.592,22.79 24.222,23.42 24.222,24.556 R6.1
NetC13_1: C13.1 U1.4 | length 4.4
  Top Layer w0.508: C13.1 41.374,8.992 U1.4
NetL1_2: L1.2 PS1.2 | length 5.1
  Top Layer w2.286: L1.2 25.195,45.798 29.835,45.798 30.093,45.541 PS1.2
NetL1_3: L1.3 PS1.1 | length 6.2
  Top Layer w2.286: L1.3 25.195,53.418 26.592,53.418 29.469,50.541 PS1.1
NetL2_2: L2.2 R7.1 | length 2.5
  Top Layer w1.016: R7.1 65.746,39.654 68.169,39.654 L2.2
NetL8_2: L8.2 R10.1 | length 8.5
  Top Layer w0.508: R10.1 62.03,30.641 63.195,31.806 63.977,31.806 65.913,33.742 L8.2
NetL9_1: L9.1 R9.2 | length 8.3
  Top Layer w0.508: L9.1 17.038,4.171 17.038,3.028 17.78,2.286 21.59,2.286 22.29,2.986 R9.2
NetQ1_1: Q1.1 R4.1 | length 4.3
  Top Layer w0.508: R4.1 44.377,21.647 46.421,19.603 Q1.1
NetQ2_1: Q2.1 R5.1 | length 18.1
  Top Layer w0.508: Q2.1 37.912,19.603 37.211,20.304 37.211,22.352 37.92,23.061 49.479,23.061 51.147,21.393 R5.1
NetR11_2: R11.2 S1.1 | length 5.9
  Top Layer w0.508: S1.1 16.962,10.961 18.762,12.762 R11.2
NetR12_2: R12.2 R13.2 T1.1 | length 8.4
  Top Layer w0.508: T1.1 41.826,32.047 40.828,31.049 R13.2 40.926,28.104 43.589,28.104 R12.2
PIN_ADC_ESP: R14.1 R15.2 U.7 | length 7.8
  Top Layer w0.762: U.7 75.745,34.655 76.454,35.364 R15.2
  Top Layer w1.016: R14.1 R15.2
RTS: Q1.2 R5.2 U1.14 | length 17.7
  Top Layer w0.508: Q1.2 48.583,22.078 49.46,21.201 49.46,21.161 50.783,19.839 50.901,19.839 R5.2 51.247,17.351 54.737,13.861 54.737,11.176 53.887,10.326 52.209,10.326 U1.14
RXD_CH: R2.1 U1.3 | length 27
  Top Layer w0.508: U1.3 46.577,10.262 47,9.839 47.084,9.839 48.641,8.282 48.641,4.053 50.535,2.159 59.117,2.159 63.374,6.416 R2.1
RXD_ESP: R3.2 U.34 | length 14.9
  Top Layer w0.508: R3.2 72.136,9.271 75.184,12.319 77.216,12.319 78.232,13.335 78.232,15.323 U.34
SCL: JP1.2 R19.2 U.36 | length 18.6
  Top Layer w0.508: JP1.2 78.484,3.554 81.278,3.554 82.677,4.953 82.677,6.922 81.752,7.847 80.798,7.847 R19.2@80.465,8.18 ; R19.2 80.479,8.193 80.645,8.359 80.645,15.196 U.36
SDA: JP1.1 R20.2 U.33 | length 16.1
  Top Layer w0.508: R20.2@76.642,8.066 76.684,8.108 76.684,9.628 v1(76.708,9.652) ; v1(76.708,13.462) 76.708,13.496 77.015,13.803 U.33
  Bottom Layer w0.508: v1(76.708,13.462) v1(76.708,9.652) 79.756,6.604 JP1.1
sensor: JP2.2 U.37 | length 34.1
  Top Layer w0.508: JP2.2 65.995,2.876 66.685,2.876 67.784,3.975 69.304,3.975 70.336,2.943 70.336,2.293 71.803,0.826 81.09,0.826 84.01,3.746 84.01,11.748 82.291,13.467 82.291,15.18 U.37
TXD_CH: R3.1 U1.2 | length 28.3
  Top Layer w0.508: U1.2 45.708,11.469 46.641,11.469 47.022,11.088 47.105,11.088 49.403,8.79 49.403,6.604 49.408,6.599 49.408,4.363 50.85,2.921 58.801,2.921 R3.1
TXD_ESP: R2.2 U.35 | length 17.5
  Top Layer w0.508: R2.2 70.932,6.416 75.692,11.176 77.535,11.176 79.555,13.196 U.35
VBAT: C16.1 J2.2 L3.2 R8.2 R17.1 | length 41.7
  Top Layer w0.762: R8.2 9.473,14.685 C16.1@12.595,14.685 ; C16.1 C16.1@12.595,14.685 ; v2(13.081,17.399) 13.081,17.365 13.716,16.73 13.716,15.705 C16.1@12.794,14.783 ; R17.1 15.791,14.783 C16.1@12.794,14.783 ; L3.2 26.981,12.305 28.424,13.748 28.424,13.819 v2(28.448,13.843) ; C16.1@12.595,14.685 12.695,14.685 C16.1@12.794,14.783
  Bottom Layer w0.762: J2.2 3.831,18.21 5.693,18.21 6.18,18.697 11.783,18.697 v2(13.081,17.399) ; 13.115,17.907 13.306,18.098 24.448,18.098 26.416,16.129 27.813,16.129 28.448,15.494 v2(28.448,13.843)
VBAT_ADC: R14.2 R17.2 | length 74.7
  Top Layer w0.762: v2(67.564,35.56) 67.598,35.56 68.487,36.449 70.541,36.449 73.589,39.497 R14.2
  Top Layer w1.016: v2(14.478,10.033) 14.478,11.367 15.692,12.582 R17.2
  Bottom Layer w1.016: v2(14.478,10.033) 27.305,10.033 52.832,35.56 v2(67.564,35.56)
VBUS_5V: C12.1 U1.16 USB1.1 | length 37.5
  Top Layer w0.254: v1(35.465,6.523) 35.465,6.42 35.656,6.229 35.656,5.108 USB1.1
  Top Layer w0.762: v2(52.07,14.605) 50.546,14.605 50.1,14.159 50.1,13.527 50.761,12.866 52.082,12.866 U1.16 ; v2(56.769,14.605) 56.771,14.603 58.743,14.603 C12.1
  Bottom Layer w0.762: v1(35.465,6.523) 34.565,7.423 34.565,7.599 34.036,8.128 34.036,10.199 37.587,13.75 51.181,13.75 52.036,14.605 v2(56.769,14.605)
Vchar5v: B1.8 C4.2 C6.2 C14.1 C19.1 T1.2 | length 54.5
  Top Layer w0.762: B1.8 v1(20.084,22.352) ; C14.1 28.128,17.28 28.128,20.185 C4.2 C6.2
  Top Layer w1.016: T1.2@44.765,31.863 46.479,30.149 C19.1
  Top Layer w1.27: C6.2@28.167,22.795 29.718,24.345 v2(29.718,24.511) ; T1.2 46.779,32.047 47.752,33.02 v1(47.752,35.433)
  Bottom Layer w1.27: v1(20.084,22.352) 22.37,24.638 29.591,24.638 v2(29.718,24.511) 30.912,25.705 30.912,27.038 34.227,30.353 34.925,30.353 40.894,36.322 46.863,36.322 v1(47.752,35.433)
VDD5V: C17.1 D1.2 JP2.1 T1.3 U2.3 | length 109.6
  Top Layer w0.762: C17.1 82.613,44.821 82.613,44.98 82.945,45.311 C17.1@82.945,45.348
  Top Layer w1.016: v2(37.397,11.943) 37.333,11.943 35.687,13.589 35.687,27.94 41.994,34.247 T1.3
  Top Layer w1.27: T1.3 57.828,48.26 68.834,48.26 71.977,51.403 D1.2 75.025,51.308 v1(77.343,51.308) ; v1(82.105,49.53) 82.931,48.704 U2.3@82.931,46.736 ; C17.1@82.945,45.348 U2.3
  Bottom Layer w1.016: v2(37.397,11.943) 47.181,2.159 60.414,2.159 60.922,2.667 JP2.1
  Bottom Layer w1.27: v1(77.343,51.308) 81.362,51.308 82.105,50.564 v1(82.105,49.53)
pads on no net: U1.7 U1.8 U1.9 U1.10 U1.11 U1.12 U1.15 U.4 U.5 U.6 U.9 U.13 U.14 U.16 U.17 U.18 U.19 U.20 U.21 U.22 U.23 U.24 U.26 U.27 U.28 U.29 U.30 U.31 U.32 USB1.4
copper on no net:
  other v3: 83.312,1.27 1.651,1.651 83.566,57.023

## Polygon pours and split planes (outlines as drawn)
GND on Top Layer "top poly" (solid, remove dead copper, pour order 0): 84.836,58.928 84.836,0 0,0 0,23.876 45.72,23.876 45.72,58.928
GND on Bottom Layer "bottom poly" (solid, remove dead copper, pour order 1): 0,23.876 0,0 84.836,0 84.836,58.928 45.72,58.928 45.72,23.495

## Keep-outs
Keep-Out Layer:
  the board outline again, w0.635

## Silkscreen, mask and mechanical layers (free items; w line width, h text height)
Top Overlay:
  text "KienNM" at 20.574,34.067 h3.05
  text "KienNM" at 54.737,7.006 h2.03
